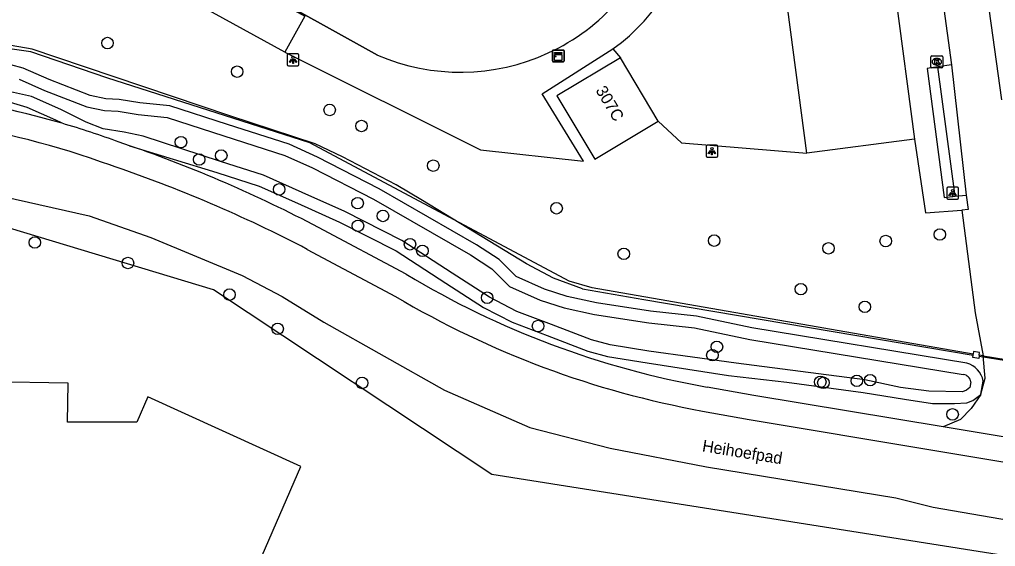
# Model space of a CAD drawing. Extents: x 162157 to 163165, y 378998 to 380775.
# Drawn here: x 162236 to 162318.7, y 379702.1 to 379746.8 of the extents above; entities that cross this region are included whole.
import ezdxf

# ---------------------------------------------------------------- set-up
doc = ezdxf.new("R2010")
doc.units = 0
for name, color, linetype in [('IMGEO_Boom', 7, 'Continuous'), ('IMGEO_Fietspad_gesloten', 7, 'Continuous'), ('IMGEO_Groenvoorziening', 7, 'Continuous'), ('IMGEO_Haag', 7, 'Continuous'), ('IMGEO_Hek', 7, 'Continuous'), ('IMGEO_Kast', 7, 'Continuous'), ('IMGEO_Kolk', 7, 'Continuous'), ('IMGEO_Lichtpunt', 7, 'Continuous'), ('IMGEO_Loofbos', 7, 'Continuous'), ('IMGEO_Muur', 7, 'Continuous'), ('IMGEO_Openbare_ruimte_label', 7, 'Continuous'), ('IMGEO_Pand', 7, 'Continuous'), ('IMGEO_Pand_nummerreeks', 7, 'Continuous'), ('IMGEO_Voetpad_gesloten', 7, 'Continuous'), ('IMGEO_Voetpad_open', 7, 'Continuous'), ('IMGEO_Waterloop', 7, 'Continuous')]:
    doc.layers.add(name, color=color, linetype=linetype)

msp = doc.modelspace()

# ---------------------------------------------------------------- linework, layer by layer
at = {"layer": 'IMGEO_Boom'}
for centre in [(162243.433, 379744.773), (162254.43, 379742.349), (162262.276, 379739.102), (162264.97, 379737.739), (162249.667, 379736.362), (162253.082, 379735.228), (162251.212, 379734.901), (162271.062, 379734.373), (162257.991, 379732.362), (162264.643, 379731.19), (162266.792, 379730.109), (162281.512, 379730.76), (162264.674, 379729.263), (162314.007, 379728.531), (162237.273, 379727.852), (162269.086, 379727.706), (162294.874, 379728.013), (162309.418, 379727.979), (162270.138, 379727.147), (162287.209, 379726.889), (162304.569, 379727.359), (162245.172, 379726.114), (162253.778, 379723.431), (162302.227, 379723.897), (162275.633, 379723.167), (162307.643, 379722.401), (162257.865, 379720.529), (162279.94, 379720.763), (162295.106, 379719.005), (162294.724, 379718.289), (162265.022, 379715.936), (162303.87, 379716.02), (162304.132, 379715.955), (162306.968, 379716.122), (162308.103, 379716.175), (162315.086, 379713.271)]:
    msp.add_circle(centre, 0.489, dxfattribs=at)
at = {"layer": 'IMGEO_Fietspad_gesloten'}
for points in [[(162245.305, 379736.068), (162244.424, 379736.369)], [(162268.773, 379725.159), (162261.33, 379729.13)], [(162260.378, 379727.269), (162267.847, 379723.281)], [(162314.3, 379712.205), (162298.239, 379714.868), (162294.268, 379715.593)], [(162293.883, 379713.556), (162297.835, 379712.825), (162406.505, 379694.666), (162426.261, 379691.023), (162431.745, 379689.857)], [(162325.622, 379710.328), (162314.3, 379712.205)]]:
    msp.add_lwpolyline(points, dxfattribs=at)
for centre, radius, start, end in [((162218.96, 379667.351), 73.567, 73.71809, 92.93475), ((162219.174, 379667.452), 71.305, 69.87551, 93.18823), ((162218.937, 379667.316), 73.607, 69.74127, 73.70882), ((162207.626, 379627.063), 115.334, 62.2482, 70.93155), ((162206.846, 379625.235), 115.224, 62.3164, 71.34284), ((162307.334, 379789.173), 74.731, 238.93594, 259.93079), ((162307.945, 379790.919), 78.631, 239.33886, 259.69768)]:
    msp.add_arc(centre, radius, start, end, dxfattribs=at)
at = {"layer": 'IMGEO_Groenvoorziening'}
for points in [[(162200.542, 379780.028), (162245.107, 379755.565), (162266.322, 379743.758)], [(162316.836, 379718.388), (162284.522, 379724.017), (162282.584, 379724.579), (162260.586, 379736.299), (162243.381, 379741.815), (162236.927, 379744.021), (162232.15, 379744.706), (162226.793, 379745.692), (162207.586, 379745.498)], [(162258.472, 379744.009), (162275.07, 379735.712), (162283.803, 379734.743), (162280.296, 379740.465), (162286.296, 379744.277)], [(162316.295, 379717.625), (162298.069, 379720.61), (162293.375, 379721.608), (162289.465, 379722.019), (162284.911, 379722.74), (162282.421, 379723.269), (162280.479, 379723.9), (162278.096, 379724.962), (162276.648, 379726.409), (162274.735, 379727.651), (162266.481, 379732.417), (162261.252, 379735.081), (162258.83, 379736.19), (162253.624, 379737.852), (162248.717, 379739.447), (162246.18, 379739.713), (162244.44, 379739.989), (162243.304, 379740.049), (162241.974, 379740.331), (162238.483, 379741.671), (162236.276, 379742.654), (162233.136, 379743.495)], [(162239.585, 379737.967), (162239.065, 379738.231), (162236.64, 379739.311), (162233.85, 379740.114), (162230.505, 379740.664), (162226.743, 379741.102), (162224.307, 379741.358), (162220.094, 379741.579), (162217.831, 379741.697), (162209.647, 379741.697), (162207.221, 379741.824), (162204.714, 379742.222)], [(162245.305, 379736.068), (162252.721, 379733.786), (162256.304, 379732.621), (162259.537, 379731.182), (162263.121, 379729.586), (162267.9, 379727.151), (162272.124, 379724.409), (162275.315, 379722.336), (162277.745, 379721.098), (162280.713, 379719.958), (162284.173, 379718.63), (162285.844, 379718.182), (162289.191, 379717.652), (162296.1, 379716.558), (162301.046, 379715.997), (162307.496, 379715.13), (162310.997, 379714.575), (162313.385, 379714.197), (162315.256, 379714.197), (162316.306, 379714.252), (162316.802, 379714.457), (162317.48, 379714.967)], [(162317.673, 379718.252), (162317.353, 379718.304)], [(162317.487, 379714.992), (162317.68, 379716.09)]]:
    msp.add_lwpolyline(points, dxfattribs=at)
for centre, radius, start, end in [((162273.362, 379760.093), 17.788, 246.68434, 342.76247), ((162315.75, 379715.741), 1.961, 10.24618, 73.87244)]:
    msp.add_arc(centre, radius, start, end, dxfattribs=at)
at = {"layer": 'IMGEO_Haag'}
msp.add_lwpolyline([(162315.296, 379731.777), (162313.835, 379742.763)], dxfattribs=at)
at = {"layer": 'IMGEO_Hek'}
for points in [[(162266.322, 379743.758), (162245.107, 379755.565), (162200.542, 379780.028)], [(162239.147, 379743.541), (162237.043, 379744.27), (162226.649, 379746.065), (162219.881, 379746.294)], [(162283.7, 379723.919), (162281.26, 379724.831), (162278.962, 379726.037), (162270.138, 379731.405), (162267.925, 379732.742), (162263.368, 379735.129), (162261.032, 379736.236), (162253.819, 379738.605), (162239.147, 379743.541)], [(162283.7, 379723.919), (162288.918, 379723.028)], [(162288.918, 379723.028), (162316.822, 379718.298)], [(162317.34, 379718.213), (162322.451, 379717.379)]]:
    msp.add_lwpolyline(points, dxfattribs=at)
msp.add_arc((162273.362, 379760.093), 17.788, 246.68434, 342.76247, dxfattribs=at)
at = {"layer": 'IMGEO_Kast'}
for p, q in [((162281.155, 379743.255), (162281.155, 379744.096)), ((162281.155, 379744.096), (162281.155, 379743.255)), ((162281.23, 379744.18), (162282.071, 379744.18)), ((162282.071, 379744.18), (162281.23, 379744.18)), ((162282.155, 379744.105), (162282.155, 379743.264)), ((162282.155, 379743.264), (162282.155, 379744.105)), ((162282.08, 379743.18), (162281.239, 379743.18)), ((162281.239, 379743.18), (162282.08, 379743.18))]:
    msp.add_line(p, q, dxfattribs=at)
for points in [[(162281.35, 379743.97), (162281.95, 379743.97), (162281.95, 379743.885), (162281.35, 379743.885), (162281.35, 379743.97)], [(162281.35, 379743.795), (162281.95, 379743.795), (162281.95, 379743.306), (162281.35, 379743.306), (162281.35, 379743.795)]]:
    msp.add_lwpolyline(points, dxfattribs=at)
msp.add_circle((162281.434, 379743.644), 0.0377, dxfattribs=at)
for centre, start, end in [((162281.233, 379744.102), 92.4484, 184.28452), ((162281.233, 379744.102), 92.4484, 184.28452), ((162282.077, 379744.102), 2.4484, 94.28452), ((162282.077, 379744.102), 2.4484, 94.28452), ((162281.233, 379743.258), 182.4484, 274.28452), ((162281.233, 379743.258), 182.4484, 274.28452), ((162282.077, 379743.258), 272.4484, 4.28452), ((162282.077, 379743.258), 272.4484, 4.28452)]:
    msp.add_arc(centre, 0.0779, start, end, dxfattribs=at)
at = {"layer": 'IMGEO_Kolk'}
for p, q in [((162313.325, 379743.684), (162314.177, 379743.684)), ((162313.25, 379742.758), (162313.25, 379743.61)), ((162313.761, 379742.904), (162313.736, 379742.904)), ((162313.738, 379743.464), (162313.763, 379743.464)), ((162314.251, 379743.61), (162314.251, 379742.758)), ((162314.177, 379742.684), (162313.325, 379742.684))]:
    msp.add_line(p, q, dxfattribs=at)
for points in [[(162313.325, 379743.684), (162314.177, 379743.684)], [(162313.25, 379742.758), (162313.25, 379743.61)], [(162313.571, 379743.384), (162313.694, 379743.384), (162313.694, 379743.233), (162313.824, 379743.384), (162313.988, 379743.384), (162313.842, 379743.233), (162313.995, 379742.984), (162313.843, 379742.984), (162313.758, 379743.148), (162313.694, 379743.081), (162313.694, 379742.984), (162313.571, 379742.984), (162313.571, 379743.384)], [(162314.251, 379743.61), (162314.251, 379742.758)], [(162314.177, 379742.684), (162313.325, 379742.684)]]:
    msp.add_lwpolyline(points, dxfattribs=at)
for centre, start, end in [((162313.327, 379743.608), 91.55205, 178.44795), ((162313.327, 379743.608), 91.55205, 178.44795), ((162314.175, 379743.608), 1.55205, 88.44795), ((162314.175, 379743.608), 1.55205, 88.44795), ((162313.327, 379742.76), 181.55205, 268.44795), ((162313.327, 379742.76), 181.55205, 268.44795), ((162314.175, 379742.76), 271.55205, 358.44795), ((162314.175, 379742.76), 271.55205, 358.44795)]:
    msp.add_arc(centre, 0.0765, start, end, dxfattribs=at)
for centre, major_axis, ratio, start_param, end_param in [((162313.737, 379743.184), (-0.387, 0.002), 0.722429, 4.712389, 7.853982), ((162313.762, 379743.184), (-0.39, 0.002), 0.717154, 1.570796, 4.712389)]:
    msp.add_ellipse(centre, major_axis=major_axis, ratio=ratio, start_param=start_param, end_param=end_param, dxfattribs=at)
at = {"layer": 'IMGEO_Lichtpunt'}
for p, q in [((162258.677, 379743.755), (162258.677, 379742.948)), ((162258.677, 379743.755), (162258.677, 379742.948)), ((162259.579, 379743.85), (162258.771, 379743.85)), ((162259.579, 379743.85), (162258.771, 379743.85)), ((162259.673, 379742.948), (162259.673, 379743.755)), ((162259.673, 379742.948), (162259.673, 379743.755)), ((162258.771, 379742.854), (162259.579, 379742.854)), ((162258.771, 379742.854), (162259.579, 379742.854)), ((162294.183, 379736.005), (162294.183, 379735.198)), ((162294.183, 379736.005), (162294.183, 379735.198)), ((162295.085, 379736.1), (162294.277, 379736.1)), ((162295.085, 379736.1), (162294.277, 379736.1)), ((162295.179, 379735.198), (162295.179, 379736.005)), ((162295.179, 379735.198), (162295.179, 379736.005)), ((162294.277, 379735.104), (162295.085, 379735.104)), ((162294.277, 379735.104), (162295.085, 379735.104)), ((162314.593, 379732.441), (162314.593, 379731.634)), ((162314.593, 379732.441), (162314.593, 379731.634)), ((162315.495, 379732.536), (162314.687, 379732.536)), ((162315.495, 379732.536), (162314.687, 379732.536)), ((162315.589, 379731.634), (162315.589, 379732.441)), ((162315.589, 379731.634), (162315.589, 379732.441)), ((162314.687, 379731.54), (162315.495, 379731.54)), ((162314.687, 379731.54), (162315.495, 379731.54))]:
    msp.add_line(p, q, dxfattribs=at)
for points in [[(162259.051, 379743.419), (162259.09, 379743.391), (162258.902, 379743.129), (162258.864, 379743.156), (162259.051, 379743.419)], [(162259.153, 379743.371), (162259.2, 379743.371), (162259.2, 379743.049), (162259.153, 379743.049), (162259.153, 379743.371)], [(162259.263, 379743.391), (162259.301, 379743.418), (162259.488, 379743.156), (162259.449, 379743.128), (162259.263, 379743.391)], [(162294.557, 379735.669), (162294.596, 379735.641), (162294.408, 379735.379), (162294.37, 379735.406), (162294.557, 379735.669)], [(162294.659, 379735.621), (162294.706, 379735.621), (162294.706, 379735.299), (162294.659, 379735.299), (162294.659, 379735.621)], [(162294.769, 379735.641), (162294.807, 379735.668), (162294.994, 379735.406), (162294.955, 379735.378), (162294.769, 379735.641)], [(162314.967, 379732.105), (162315.006, 379732.077), (162314.818, 379731.815), (162314.78, 379731.842), (162314.967, 379732.105)], [(162315.179, 379732.077), (162315.217, 379732.104), (162315.404, 379731.842), (162315.365, 379731.814), (162315.179, 379732.077)], [(162315.069, 379732.057), (162315.116, 379732.057), (162315.116, 379731.735), (162315.069, 379731.735), (162315.069, 379732.057)]]:
    msp.add_lwpolyline(points, dxfattribs=at)
for centre in [(162259.176, 379743.553), (162294.682, 379735.803), (162315.092, 379732.239)]:
    msp.add_circle(centre, 0.0994, dxfattribs=at)
for centre, start, end in [((162258.771, 379743.755), 90, 180), ((162258.771, 379743.755), 90, 180), ((162259.579, 379743.755), 0, 90), ((162259.579, 379743.755), 0, 90), ((162258.771, 379742.948), 180, 270), ((162258.771, 379742.948), 180, 270), ((162259.579, 379742.948), 270, 0), ((162259.579, 379742.948), 270, 360), ((162294.277, 379736.005), 90, 180), ((162294.277, 379736.005), 90, 180), ((162295.085, 379736.005), 0, 90), ((162295.085, 379736.005), 0, 90), ((162294.277, 379735.198), 180, 270), ((162294.277, 379735.198), 180, 270), ((162295.085, 379735.198), 270, 0), ((162295.085, 379735.198), 270, 360), ((162314.687, 379732.441), 90, 180), ((162314.687, 379732.441), 90, 180), ((162315.495, 379732.441), 0, 90), ((162315.495, 379732.441), 0, 90), ((162314.687, 379731.634), 180, 270), ((162314.687, 379731.634), 180, 270), ((162315.495, 379731.634), 270, 0), ((162315.495, 379731.634), 270, 360)]:
    msp.add_arc(centre, 0.0946, start, end, dxfattribs=at)
at = {"layer": 'IMGEO_Loofbos'}
for points in [[(162200.706, 379732.277), (162205.491, 379732.528), (162214.541, 379733.002), (162226.745, 379733.002), (162231.259, 379732.528), (162235.614, 379731.527), (162241.895, 379730.106), (162247.114, 379728.274), (162254.858, 379725.049), (162258.235, 379723.285), (162261.79, 379721.082), (162272, 379715.314), (162279.233, 379712.147), (162286.048, 379710.401), (162294.223, 379708.812), (162310.274, 379706.198), (162313.432, 379705.394), (162326.545, 379703.142), (162329.924, 379702.799)], [(162334.223, 379698.94), (162276.018, 379708.183), (162252.426, 379723.827), (162232.664, 379729.795), (162201.08, 379730.479)]]:
    msp.add_lwpolyline(points, dxfattribs=at)
at = {"layer": 'IMGEO_Muur'}
for points in [[(162317.353, 379718.304), (162317.34, 379718.213), (162317.31, 379718), (162316.79, 379718.091), (162316.822, 379718.298), (162316.836, 379718.388)], [(162317.353, 379718.304), (162317.383, 379718.517), (162316.869, 379718.597), (162316.836, 379718.388)]]:
    msp.add_lwpolyline(points, dxfattribs=at)
at = {"layer": 'IMGEO_Pand'}
for points in [[(162302.724, 379735.425), (162301.13, 379747.629), (162310.261, 379748.822), (162311.854, 379736.618)], [(162286.928, 379743.522), (162281.544, 379740.303), (162284.754, 379734.934), (162290.138, 379738.153)], [(162290.138, 379738.153), (162286.928, 379743.522)], [(162311.854, 379736.618), (162302.724, 379735.425)], [(162255.065, 379697.836), (162259.822, 379708.842), (162246.86, 379714.754), (162245.928, 379712.598), (162240.045, 379712.614), (162240.098, 379715.933), (162233.536, 379716.037), (162233.306, 379715.96), (162233.263, 379709.148), (162223.533, 379709.187), (162223.554, 379716.023), (162223.33, 379716.015), (162208.063, 379716.088), (162208.054, 379710.024), (162208.049, 379706.603), (162208.219, 379706.603), (162208.071, 379651.682)]]:
    msp.add_lwpolyline(points, dxfattribs=at)
at = {"layer": 'IMGEO_Voetpad_gesloten'}
for points in [[(162308.342, 379818.234), (162319.23, 379739.952)], [(162312.638, 379758.611), (162313.486, 379751.686), (162313.807, 379751.65), (162314.999, 379742.94)], [(162314.999, 379742.94), (162316.244, 379731.87)], [(162316.244, 379731.87), (162316.4, 379730.646), (162315.86, 379730.604)], [(162315.86, 379730.604), (162317.006, 379721.885), (162317.673, 379718.252)], [(162317.673, 379718.252), (162321.707, 379717.594), (162322.285, 379717.503)]]:
    msp.add_lwpolyline(points, dxfattribs=at)
at = {"layer": 'IMGEO_Voetpad_open'}
for points in [[(162244.456, 379751.721), (162246.14, 379754.783), (162260.156, 379747.07), (162258.472, 379744.009)], [(162258.472, 379744.009), (162244.456, 379751.721)], [(162286.296, 379744.277), (162286.928, 379743.522)], [(162314.999, 379742.94), (162313.835, 379742.763)], [(162313.835, 379742.763), (162312.925, 379742.625), (162314.36, 379731.685), (162315.296, 379731.777)], [(162290.138, 379738.153), (162292.108, 379736.3), (162302.724, 379735.425)], [(162311.854, 379736.618), (162312.79, 379730.368), (162315.86, 379730.604)], [(162315.296, 379731.777), (162316.244, 379731.87)], [(162317.487, 379714.992), (162317.854, 379716.332), (162317.673, 379718.252)], [(162317.48, 379714.967), (162316.676, 379713.773), (162315.759, 379712.85), (162314.3, 379712.205)], [(162317.48, 379714.967), (162317.487, 379714.992)]]:
    msp.add_lwpolyline(points, dxfattribs=at)
msp.add_arc((162276.161, 379758.307), 17.307, 305.84362, 352.61508, dxfattribs=at)
at = {"layer": 'IMGEO_Waterloop'}
for points in [[(162316.645, 379716.03), (162316.541, 379715.543), (162316.278, 379715.322), (162315.924, 379715.176), (162313.082, 379715.232), (162310.683, 379715.554), (162307.645, 379716.196), (162296.749, 379717.606), (162289.347, 379718.64), (162286.053, 379719.162), (162284.483, 379719.583), (162281.071, 379720.892), (162278.153, 379722.012), (162275.816, 379723.203), (162272.668, 379725.247), (162268.401, 379728.018), (162263.552, 379730.489), (162259.944, 379732.095), (162256.663, 379733.556), (162253.03, 379734.737), (162246.47, 379736.868), (162244.838, 379737.215), (162243.069, 379737.495), (162241.623, 379738.05), (162239.496, 379739.134), (162237, 379740.245), (162230.621, 379741.657)], [(162235.941, 379741.709), (162238.101, 379740.747), (162241.689, 379739.369), (162243.173, 379739.054), (162244.335, 379738.993), (162246.049, 379738.722), (162248.508, 379738.463), (162253.315, 379736.901), (162258.462, 379735.229), (162260.821, 379734.178), (162266.004, 379731.538), (162274.212, 379726.799), (162276.015, 379725.628), (162277.519, 379724.123), (162280.12, 379722.966), (162282.162, 379722.302), (162284.729, 379721.757), (162289.335, 379721.027), (162293.218, 379720.619), (162297.898, 379719.624), (162315.994, 379716.663)]]:
    msp.add_lwpolyline(points, dxfattribs=at)
msp.add_arc((162315.873, 379715.887), 0.785, 10.47592, 81.1304, dxfattribs=at)

# ---------------------------------------------------------------- texts
at = {"layer": 'IMGEO_Openbare_ruimte_label'}
msp.add_text('Heihoefpad', height=1, rotation=350.73548, dxfattribs=at).set_placement((162293.812, 379710.136))
at = {"layer": 'IMGEO_Pand_nummerreeks'}
msp.add_text('307C', height=1, rotation=300.87649, dxfattribs=at).set_placement((162284.787, 379740.77))

doc.saveas('drawing.dxf')
